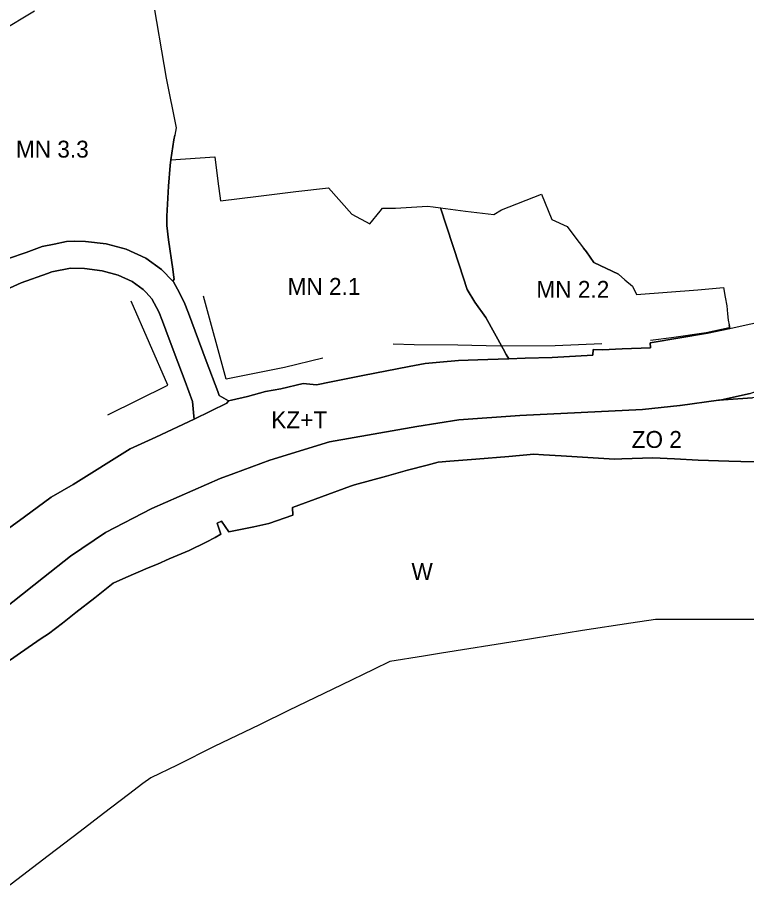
# Model space of a CAD drawing. Extents: x 7421359 to 7422386, y 5546414 to 5547388.
# Drawn here: x 7421829.1 to 7422044.6, y 5546600.9 to 5546861.7 of the extents above; entities that cross this region are included whole.
import ezdxf

# ---------------------------------------------------------------- set-up
doc = ezdxf.new("R2010")
doc.units = 0
for name, color, linetype in [('linie_rozgraniczajace', 7, 'Continuous'), ('linie_zabudowy', 7, 'Continuous'), ('oznaczenia_przeznaczen', 7, 'Continuous')]:
    doc.layers.add(name, color=color, linetype=linetype)

msp = doc.modelspace()

# ---------------------------------------------------------------- linework, layer by layer
at = {"layer": 'linie_rozgraniczajace'}
for points in [[(7421868.77, 5546868.77), (7421872.97, 5546843.81), (7421875.95, 5546829.15), (7421875.53, 5546826.94), (7421875.28, 5546825.6), (7421874.42, 5546819.64), (7421874.17, 5546817.94), (7421873.71, 5546811.83), (7421873.25, 5546802.98), (7421873.16, 5546800.23), (7421873.74, 5546795.99), (7421875.01, 5546787.31), (7421875.31, 5546784.83), (7421875.42, 5546784.31), (7421874.95, 5546783.78), (7421871.67, 5546787.18), (7421866.95, 5546790.6), (7421861.21, 5546793.2), (7421855.31, 5546794.76), (7421849.16, 5546795.49), (7421845.82, 5546795.58), (7421843.53, 5546795.49), (7421839.9, 5546794.74), (7421836.32, 5546793.99), (7421831.57, 5546792.27), (7421826.36, 5546790.44)], [(7421823.97, 5546857.6), (7421834.05, 5546863.7)], [(7421826.36, 5546790.44), (7421831.57, 5546792.27), (7421836.32, 5546793.99), (7421839.9, 5546794.74), (7421843.53, 5546795.49), (7421845.82, 5546795.58), (7421849.16, 5546795.49), (7421855.31, 5546794.76), (7421861.21, 5546793.2), (7421866.95, 5546790.6), (7421871.67, 5546787.18), (7421874.95, 5546783.78), (7421875.16, 5546783.57), (7421876.4, 5546781.44), (7421878.34, 5546777.58), (7421879.59, 5546774.25), (7421881.56, 5546769), (7421884.86, 5546760.19), (7421888.27, 5546751.15), (7421888.71, 5546749.97), (7421891.46, 5546748.32), (7421890.98, 5546747.67), (7421881.3, 5546742.9), (7421881.2, 5546743.85), (7421880.81, 5546748.18), (7421878.61, 5546754.05), (7421876.5, 5546759.76), (7421873.91, 5546766.6), (7421871.91, 5546771.94), (7421870.87, 5546774.68), (7421868.81, 5546778.58), (7421867.12, 5546780.37), (7421866.17, 5546781.3), (7421862.97, 5546783.63), (7421858.77, 5546785.54), (7421854.09, 5546786.79), (7421848.83, 5546787.46), (7421844.72, 5546787.61), (7421839.25, 5546786.47), (7421837.97, 5546786.04), (7421830.11, 5546783.27), (7421820.08, 5546778.69)], [(7421820.08, 5546778.69), (7421830.11, 5546783.27), (7421837.97, 5546786.04), (7421839.25, 5546786.47), (7421844.72, 5546787.61), (7421848.83, 5546787.46), (7421854.09, 5546786.79), (7421858.77, 5546785.54), (7421862.97, 5546783.63), (7421866.17, 5546781.3), (7421867.12, 5546780.37), (7421868.81, 5546778.58), (7421870.87, 5546774.68), (7421871.91, 5546771.94), (7421873.91, 5546766.6), (7421876.5, 5546759.76), (7421878.61, 5546754.05), (7421880.81, 5546748.18), (7421881.2, 5546743.85), (7421881.3, 5546742.9), (7421881.29, 5546742.9), (7421869.97, 5546737.67), (7421862.32, 5546734.21), (7421845.48, 5546723.62), (7421839.02, 5546719.85), (7421831.08, 5546714.03), (7421826.4, 5546710.61)], [(7421826.4, 5546710.61), (7421831.08, 5546714.03), (7421839.02, 5546719.85), (7421845.48, 5546723.62), (7421862.32, 5546734.21), (7421869.97, 5546737.67), (7421881.29, 5546742.9), (7421881.3, 5546742.9), (7421890.98, 5546747.67), (7421891.46, 5546748.32), (7421892.37, 5546748.55), (7421897.08, 5546749.66), (7421902.4, 5546751.1), (7421906.88, 5546751.87), (7421913.54, 5546753.46), (7421917.43, 5546753.07), (7421921.8, 5546753.99), (7421931.13, 5546755.9), (7421944.84, 5546758.48), (7421949.57, 5546759.44), (7421953.9, 5546759.83), (7421959.42, 5546760.31), (7421965.18, 5546760.48), (7421974.11, 5546760.75), (7421974.35, 5546760.77), (7421979.12, 5546761), (7421987.18, 5546761.22), (7421999.16, 5546761.83), (7421999.26, 5546763.5), (7422002.03, 5546763.48), (7422007.88, 5546763.7), (7422016.21, 5546764.04), (7422016.15, 5546765.48), (7422033.1, 5546768.36), (7422039.64, 5546769.77), (7422039.64, 5546769.77), (7422040.95, 5546770.01), (7422040.95, 5546770.01), (7422050.78, 5546772.18)], [(7422045.72, 5546750.58), (7422037.24, 5546748.68), (7422036.62, 5546748.6), (7422036.36, 5546748.53), (7422025.01, 5546747.03), (7422024.88, 5546747.02), (7422024.85, 5546747.01), (7422013.85, 5546745.76), (7421977.57, 5546744.02), (7421959.51, 5546742.79), (7421947.15, 5546740.79), (7421921.31, 5546736.21), (7421903.7, 5546730.79), (7421893, 5546726.89), (7421889.02, 5546725.44), (7421868.73, 5546716.55), (7421855.05, 5546709.38), (7421844.71, 5546702.44), (7421836.73, 5546696.13), (7421797.48, 5546665.03)], [(7421797.48, 5546665.03), (7421836.73, 5546696.13), (7421844.71, 5546702.44), (7421855.05, 5546709.38), (7421868.73, 5546716.55), (7421889.02, 5546725.44), (7421893, 5546726.89), (7421903.7, 5546730.79), (7421921.31, 5546736.21), (7421947.15, 5546740.79), (7421959.51, 5546742.79), (7421977.57, 5546744.02), (7422013.85, 5546745.76), (7422024.85, 5546747.01), (7422024.88, 5546747.02), (7422025.01, 5546747.03), (7422036.36, 5546748.53), (7422046.34, 5546749.25)], [(7421822.39, 5546668.64), (7421832.22, 5546675.46), (7421836.07, 5546678.11), (7421838.18, 5546679.47), (7421842.31, 5546682.66), (7421846.26, 5546685.74), (7421851.87, 5546690.15), (7421857.36, 5546694.46), (7421861.11, 5546696.08), (7421867.73, 5546698.95), (7421870.42, 5546700.11), (7421873.87, 5546701.6), (7421879.77, 5546704.13), (7421884.82, 5546706.61), (7421887.46, 5546707.96), (7421889.2, 5546708.93), (7421888.1, 5546712.19), (7421889.35, 5546712.8), (7421891.51, 5546709.63), (7421898.91, 5546711.12), (7421903.39, 5546712.07), (7421910.5, 5546714.6), (7421910.37, 5546716.87), (7421927.52, 5546723.16), (7421928.68, 5546723.51), (7421938.12, 5546726.09), (7421942.31, 5546727.23), (7421944.41, 5546727.85), (7421950.16, 5546729.38), (7421953.39, 5546730.19), (7421956.92, 5546730.49), (7421964.58, 5546731.16), (7421974.28, 5546731.93), (7421981.76, 5546732.56), (7421984.54, 5546732.4), (7421989.79, 5546732.12), (7421999.22, 5546731.5), (7422005.62, 5546731.11), (7422007.73, 5546731.18), (7422016.95, 5546731.55), (7422023.27, 5546731.24), (7422030.29, 5546730.86), (7422039.39, 5546730.51), (7422042.91, 5546730.4), (7422048.02, 5546730.29)], [(7422048.02, 5546730.29), (7422042.91, 5546730.4), (7422039.39, 5546730.51), (7422030.29, 5546730.86), (7422023.27, 5546731.24), (7422016.95, 5546731.55), (7422007.73, 5546731.18), (7422005.62, 5546731.11), (7421999.22, 5546731.5), (7421989.79, 5546732.12), (7421984.54, 5546732.4), (7421981.76, 5546732.56), (7421974.28, 5546731.93), (7421964.58, 5546731.16), (7421956.92, 5546730.49), (7421953.39, 5546730.19), (7421950.16, 5546729.38), (7421944.41, 5546727.85), (7421942.31, 5546727.23), (7421938.12, 5546726.09), (7421928.68, 5546723.51), (7421927.52, 5546723.16), (7421910.37, 5546716.87), (7421910.5, 5546714.6), (7421903.39, 5546712.07), (7421898.91, 5546711.12), (7421891.51, 5546709.63), (7421889.35, 5546712.8), (7421888.1, 5546712.19), (7421889.2, 5546708.93), (7421887.46, 5546707.96), (7421884.82, 5546706.61), (7421879.77, 5546704.13)], [(7421879.77, 5546704.13), (7421873.87, 5546701.6), (7421870.42, 5546700.11), (7421867.73, 5546698.95), (7421861.11, 5546696.08), (7421857.36, 5546694.46), (7421851.87, 5546690.15), (7421846.26, 5546685.74), (7421842.31, 5546682.66), (7421838.18, 5546679.47), (7421836.07, 5546678.11), (7421832.22, 5546675.46), (7421822.39, 5546668.64)], [(7422061.95, 5546683.68), (7422042.46, 5546683.67), (7422034.12, 5546683.68), (7422025.19, 5546683.68), (7422017.68, 5546683.73), (7422010.45, 5546682.6), (7421996.07, 5546680.41), (7421976.77, 5546677.25), (7421954.4, 5546673.72), (7421949.13, 5546672.85), (7421939.18, 5546671.25), (7421934.27, 5546668.91), (7421924.93, 5546664.36), (7421909.15, 5546656.81), (7421900.56, 5546652.59), (7421887.24, 5546646.09), (7421876.26, 5546640.64), (7421868.43, 5546636.86), (7421866.11, 5546635.22), (7421861.84, 5546631.95), (7421854.44, 5546626.29), (7421847.63, 5546621.01), (7421838.09, 5546613.77), (7421821.21, 5546600.93)]]:
    msp.add_lwpolyline(points, dxfattribs=at)
for points in [[(7421875.53, 5546826.94), (7421875.28, 5546825.6), (7421874.42, 5546819.64), (7421874.42, 5546819.64), (7421875.28, 5546825.6)], [(7421887.4, 5546820.54), (7421888.31, 5546813.38), (7421889.05, 5546807.52), (7421900.34, 5546808.91), (7421911.33, 5546810.26), (7421920.96, 5546811.4), (7421927.89, 5546803.57), (7421927.89, 5546803.57), (7421933.25, 5546800.72), (7421936.29, 5546804.43), (7421937.02, 5546805.31), (7421940.79, 5546805.39), (7421940.79, 5546805.39), (7421950.31, 5546805.91), (7421951.96, 5546805.71), (7421954.13, 5546805.43), (7421959.6, 5546788.54), (7421962, 5546781.34), (7421964.27, 5546777.52), (7421967.52, 5546773.01), (7421972.64, 5546763.73), (7421973.58, 5546762.1), (7421974.35, 5546760.77), (7421974.11, 5546760.75), (7421965.18, 5546760.48), (7421959.42, 5546760.31), (7421953.9, 5546759.83), (7421949.57, 5546759.44), (7421944.84, 5546758.48), (7421931.13, 5546755.9), (7421921.8, 5546753.99), (7421917.43, 5546753.07), (7421913.54, 5546753.46), (7421906.88, 5546751.87), (7421902.4, 5546751.1), (7421897.08, 5546749.66), (7421892.37, 5546748.55), (7421891.46, 5546748.32), (7421888.71, 5546749.97), (7421888.27, 5546751.15), (7421884.86, 5546760.19), (7421881.56, 5546769), (7421879.59, 5546774.25), (7421878.34, 5546777.58), (7421876.4, 5546781.44), (7421875.16, 5546783.57), (7421874.95, 5546783.78), (7421875.42, 5546784.31), (7421875.31, 5546784.83), (7421875.01, 5546787.31), (7421873.74, 5546795.99), (7421873.16, 5546800.23), (7421873.25, 5546802.98), (7421873.71, 5546811.83), (7421874.17, 5546817.94), (7421874.42, 5546819.64), (7421874.42, 5546819.64), (7421874.42, 5546819.64)], [(7421984.01, 5546809.46), (7421987.03, 5546801.96), (7421991.55, 5546799.89), (7421993.89, 5546796.85), (7421996.44, 5546793.51), (7421997.27, 5546792.42), (7421999.45, 5546789.24), (7422006.74, 5546785.85), (7422008.6, 5546784.2), (7422010.93, 5546782.24), (7422012.03, 5546779.86), (7422030.24, 5546781.15), (7422037.78, 5546781.85), (7422038.27, 5546779.06), (7422038.78, 5546776.42), (7422038.78, 5546776.42), (7422039.01, 5546774.05), (7422039.01, 5546774.05), (7422039.22, 5546772.22), (7422039.46, 5546770.84), (7422039.64, 5546769.77), (7422033.1, 5546768.36), (7422016.15, 5546765.48), (7422016.21, 5546764.04), (7422007.88, 5546763.7), (7422002.03, 5546763.48), (7421999.26, 5546763.5), (7421999.16, 5546761.83), (7421987.18, 5546761.22), (7421979.12, 5546761), (7421974.35, 5546760.77), (7421973.58, 5546762.1), (7421972.64, 5546763.73), (7421967.52, 5546773.01), (7421964.27, 5546777.52), (7421962, 5546781.34), (7421959.6, 5546788.54), (7421954.13, 5546805.43), (7421961.51, 5546804.5), (7421969.94, 5546803.44), (7421972.2, 5546804.83)], [(7421996.44, 5546793.51), (7421997.27, 5546792.42), (7421999.45, 5546789.24), (7421997.27, 5546792.42)], [(7421999.45, 5546789.24), (7422006.74, 5546785.85), (7422006.74, 5546785.85)], [(7422106.41, 5546772.46), (7422106.75, 5546771.22), (7422107.21, 5546769.01), (7422108.19, 5546763.12), (7422109.72, 5546752.8), (7422109.9, 5546751.15), (7422102.8, 5546751.01), (7422086.53, 5546750.61), (7422068.02, 5546750), (7422046.34, 5546749.25), (7422036.36, 5546748.53), (7422036.62, 5546748.6), (7422037.24, 5546748.68), (7422045.72, 5546750.58), (7422046.17, 5546750.73), (7422046.51, 5546750.79), (7422064.7, 5546756.46), (7422065.28, 5546756.69), (7422065.41, 5546756.71), (7422089.28, 5546766.2)], [(7422039.46, 5546770.84), (7422039.64, 5546769.77), (7422039.64, 5546769.77)]]:
    msp.add_lwpolyline(points, close=True, dxfattribs=at)
at = {"layer": 'linie_zabudowy'}
for points in [[(7421919.38, 5546760.94), (7421907.97, 5546758.23), (7421890.77, 5546754.75), (7421884.08, 5546779.37)], [(7421855.72, 5546744.19), (7421873.5, 5546752.99), (7421862.69, 5546777.84)], [(7422039.44, 5546769.99), (7422032.66, 5546768.51), (7422022.46, 5546766.97), (7422016.21, 5546766.19)], [(7422001.82, 5546765.21), (7421988.07, 5546764.65), (7421971.75, 5546764.53), (7421959.21, 5546764.81), (7421946.36, 5546764.95), (7421940.13, 5546765.09)]]:
    msp.add_lwpolyline(points, dxfattribs=at)

# ---------------------------------------------------------------- texts
at = {"layer": 'oznaczenia_przeznaczen'}
for s, p in [('MN 3.3', (7421828.569385, 5546820.300011)), ('MN 2.1', (7421908.907118, 5546779.710011)), ('MN 2.2', (7421982.481328, 5546778.830011)), ('KZ+T', (7421904.077892, 5546740.254483)), ('ZO 2', (7422010.641897, 5546734.4475)), ('W', (7421945.538269, 5546695.395303))]:
    msp.add_text(s, height=4.999998, dxfattribs=at).set_placement(p)

doc.saveas('drawing.dxf')
